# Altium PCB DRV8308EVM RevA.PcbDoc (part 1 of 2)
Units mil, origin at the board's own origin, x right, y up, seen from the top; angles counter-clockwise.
Board outline 4724.41 x 2952.76 mil, 2 copper layers (Top Layer, Bottom Layer), stack 62 mil thick; 110 components, 81 nets, 346 pads, 592 vias.
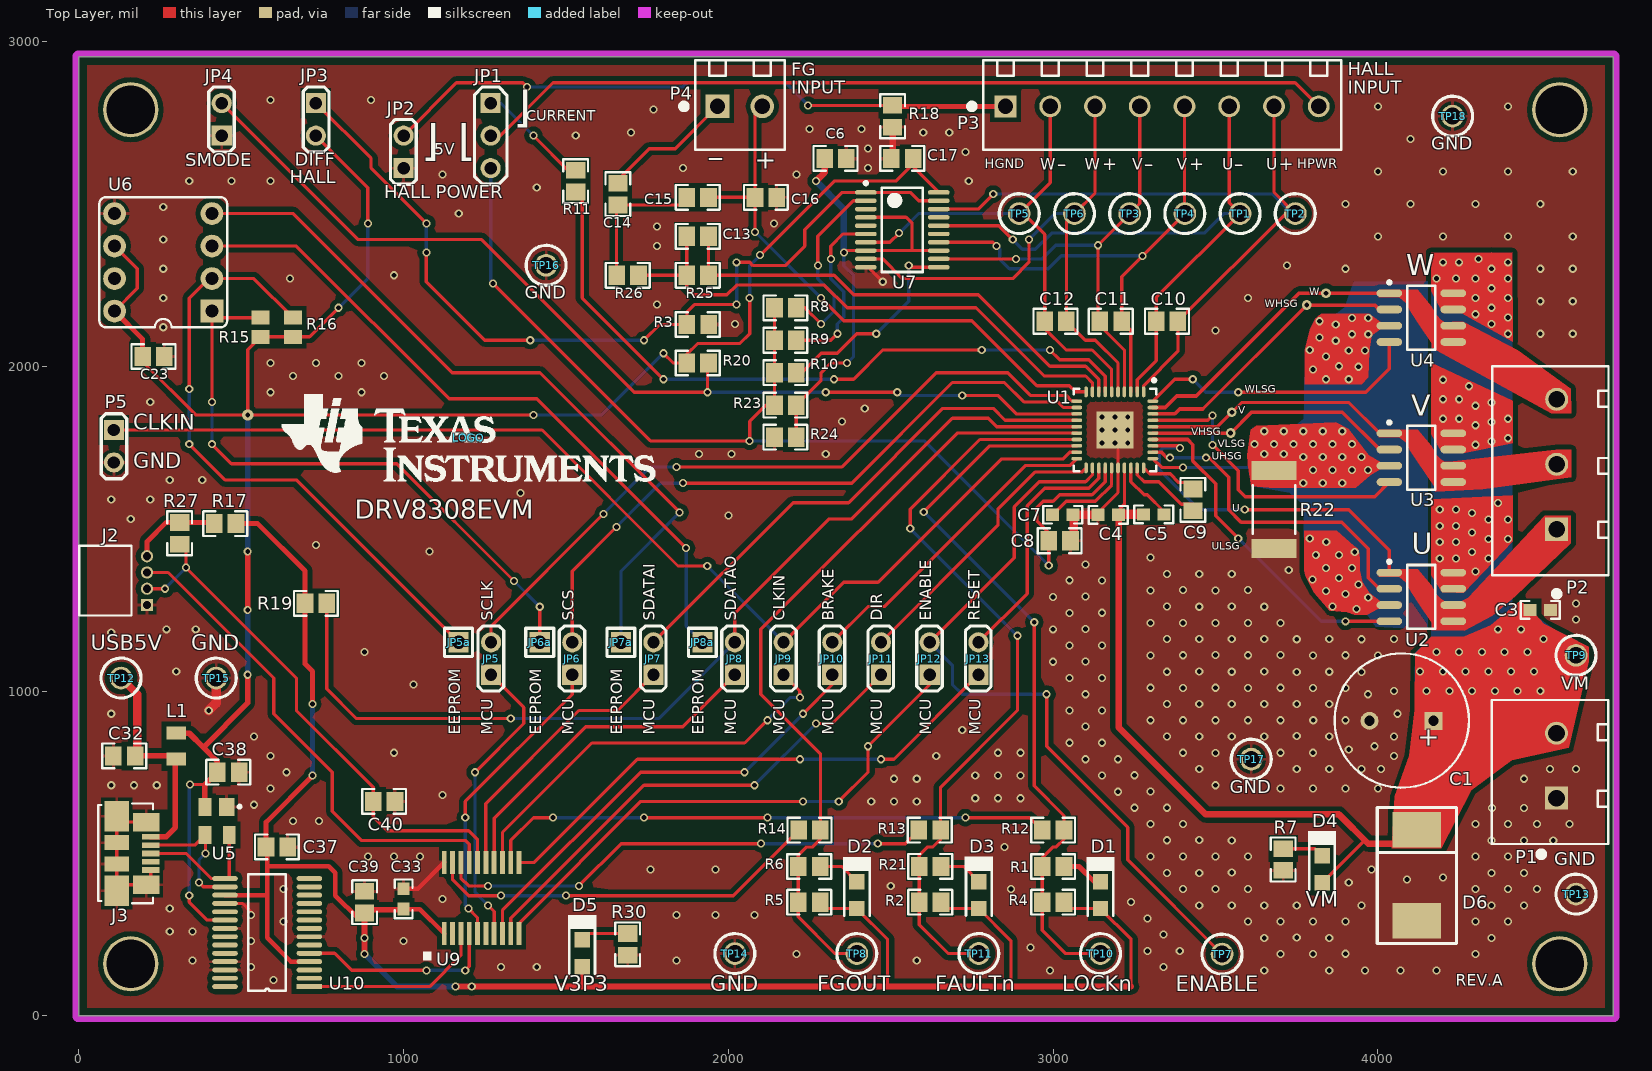
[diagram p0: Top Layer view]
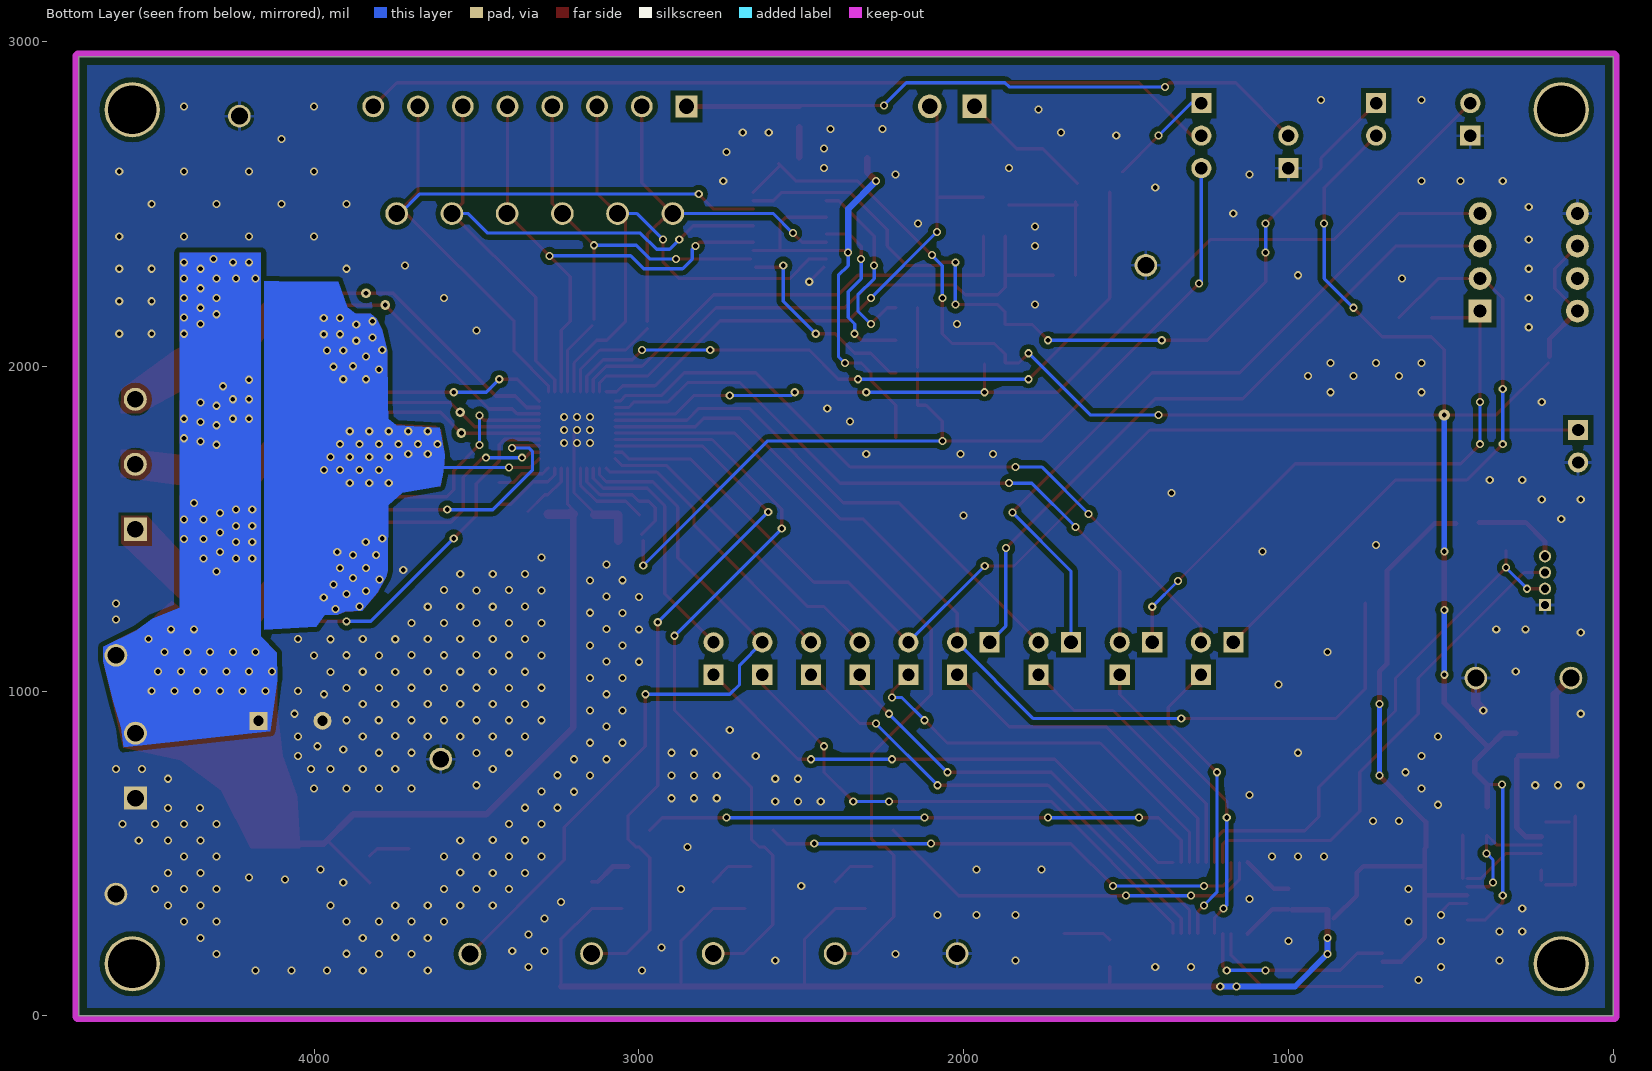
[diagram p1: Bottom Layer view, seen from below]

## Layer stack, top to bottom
Top Layer: signal copper 1.4
Dielectric: core 59.2, FR-4, Dk 4.8
Bottom Layer: signal copper 1.4

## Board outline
0,0 4724.41,0 4724.41,2952.76 0,2952.76

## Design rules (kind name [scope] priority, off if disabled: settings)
AcuteAngle [All] p1: minimum=1.50000000000000E+0001 checktracksonly=FALSE
AssemblyTestPointUsage [All] p1: valid=2
Clearance Clearance_BoardEdge_MountingHoles [OnCopper and InComponentClass('Mounting Holes') vs IsKeepOut] p1: gap=40
Clearance Clearance_BoardEdge_Poly [OnCopper and InPoly vs IsKeepOut] p2: gap=25
Clearance Clearance_BoardEdge [OnCopper and Not InComponentClass('Logo') and not InComponentClass('FiducialMark') and not InRegion(1000,500,4000,800) and Not IsKeepout vs IsKeepOut] p3: gap=75
Clearance Clearance_Poly [InPolygon] p4: gap=15
Clearance [All] p5: gap=8
ComponentClearance ComponentClearance_Logo [InComponentClass('Logo')] p1: gap=50 collisioncheckmode=3 verticalgap=10 showdistances=FALSE
ComponentClearance ComponentClearance_ScrewToNut [(HasFootprint('NY PMS 440 0025 PH')) vs (HasFootprint('Keystone_1902C'))] p2: gap=5 collisioncheckmode=3 verticalgap=10 showdistances=FALSE
ComponentClearance ComponentClearance_MountingHoles [InComponentClass('Mounting Holes')] p3: gap=250 collisioncheckmode=3 verticalgap=100000 showdistances=FALSE
ComponentClearance ComponentClearance_SmallPassives [HasFootprint('0201*') or HasFootprint('0402*') or HasFootprint('0508') or HasFootprint('0603*') or HasFootprint('0612') or HasFootprint('0805*') or HasFootprint('0815*') or HasFootprint('0830*') or HasFootprint('1206*') or HasFootprint('1210*') or HasFootprint('1808*') or HasFootprint('1812*') or HasFootprint('1825*') or HasFootprint('2010*') or HasFootprint('2220*') or HasFootprint('2225*') or HasFootprint('2512*') or HasFootprint('2728*') or HasFootprint('3518*') vs HasFootprint('0201*') or HasFootprint('0402*') or HasFootprint('0508') or HasFootprint('0603*') or HasFootprint('0612') or HasFootprint('0805*') or HasFootprint('0815*') or HasFootprint('0830*') or HasFootprint('1206*') or HasFootprint('1210*') or HasFootprint('1808*') or HasFootprint('1812*') or HasFootprint('1825*') or HasFootprint('2010*') or HasFootprint('2220*') or HasFootprint('2225*') or HasFootprint('2512*') or HasFootprint('2728*') or HasFootprint('3518*')] p4: gap=20 collisioncheckmode=3 verticalgap=10 showdistances=FALSE
ComponentClearance ComponentClearance_THtoSMT [IsThruComponent vs IsSMTComponent] p5: gap=54.33 collisioncheckmode=3 verticalgap=30 showdistances=FALSE
ComponentClearance ComponentClearance_THtoTH [IsThruComponent vs IsThruComponent] p6: gap=0 collisioncheckmode=3 verticalgap=30 showdistances=FALSE
ComponentClearance [All] p7: gap=40 collisioncheckmode=3 verticalgap=10 showdistances=FALSE
DiffPairsRouting [All] p1: maxlimit=100 minlimit=10 mostfreqgap=10 maxuncoupledlength=1000
FabricationTestPointUsage TestPointUsage [All] p1: valid=2 allowmultiple=FALSE
FabricationTestpoint Testpoint [All] p1: side=3 testpointundercomponent=TRUE minsize=40 maxsize=100 preferedsize=60 minholesize=0 maxholesize=40 preferedholesize=32 testpointgrid=1 allowsidetop=TRUE allowsidebottom=TRUE usegrid=TRUE gridtolerance=0.01
FanoutControl Fanout_LCC [IsLCC] p1: bgadir=Out bgaviamode=Centered fanoutstyle=Auto fanoutdirection=Alternating viagrid=1 // Fanout_LCC (Default Rule)
FanoutControl Fanout_BGA [IsBGA] p2: bgadir=Out bgaviamode=Centered fanoutstyle=Auto fanoutdirection=Alternating viagrid=1 // Fanout_BGA (Default Rule)
FanoutControl Fanout_Default [All] p4: bgadir=Out bgaviamode=Centered fanoutstyle=Auto fanoutdirection=Alternating viagrid=1 // Fanout_Default (Default Rule)
FanoutControl Fanout_Small [(CompPinCount < 5)] p5: bgadir=Out bgaviamode=Centered fanoutstyle=Auto fanoutdirection=OutThenIn viagrid=1 // Fanout_Small (Default Rule)
HoleSize [All] p1: absolutevalues=TRUE maxlimit=251 minlimit=8 maxpercent=80.000 minpercent=20.000
MinimumAnnularRing [All] p1: minimumring=5
MinimumSolderMaskSliver MinimumSolderMaskSliver_Logo [InComponentClass('Logo') vs InComponentClass('Logo')] p1: minsoldermaskwidth=0.7
MinimumSolderMaskSliver [All] p2: minsoldermaskwidth=3
PlaneConnect [All] p1: planeconnectstyle=Relief reliefexpansion=10 reliefentries=4 reliefconductorwidth=10 reliefairgap=10
PolygonConnect PolygonConnect_1 [IsNamedPolygon('Top GND plane') or IsNamedPolygon('Bottom GND plane') vs not ( InComponent('U1') or InComponent('C1') or       InComponent('C2') or InComponent('P1') or       InComponent('D6') or InComponent('R22') or       InComponent('TP13') or   InComponent('C3') or       InComponent('U11') or       IsStitchingVia or IsVia)] p1: connectstyle=Relief reliefconductorwidth=10 reliefentries=4 polygonreliefangle="90 Angle" airgapwidth=10
PolygonConnect [All] p2: connectstyle=Direct reliefconductorwidth=10 reliefentries=4 polygonreliefangle="90 Angle" airgapwidth=10
RoutingVias [All] p1: holewidth=16 width=34 viastyle="Through Hole" minholewidth=8 minwidth=25 maxholewidth=40 maxwidth=65
SMDToCorner [All] p1: distance=0
SilkToSilkClearance [All] p1: silktosilkclearance=3
SilkscreenOverComponentPads [All] p1: minsilkscreentomaskgap=2
SolderMaskExpansion [All] p1: expansion=3
Width [All] p1: maxlimit=100 minlimit=6 preferedwidth=10 checkconnectedcopper=TRUE
14 further rules are at their usual default settings.

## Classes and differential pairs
component class Logo: LOGO

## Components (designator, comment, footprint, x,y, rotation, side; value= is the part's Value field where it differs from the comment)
C1 "220uF" UVZ1J221MPD_fp 4080,910 r180 top
C3 "06031C272JAT2A" 0603 4500,1250 r0 top
C4 "06031C272JAT2A" 0603 3169.91,1542.7 r180 top
C5 "06031C272JAT2A" 0603 3309.91,1544.02 r180 top
C6 "" 0805#1 2330,2640 r0 top
C7 "06031C272JAT2A" 0603 3029.91,1542.7 r0 top
C8 "" 0805#1 3019.91,1462.7 r180 top
C9 "" 0805#1 3430.22,1588.43 r90 top
C10 "0.1uF" 0805#1 3350.77,2138.54 r0 top
C11 "0.1uF" 0805#1 3177.46,2138.54 r0 top
C12 "0.1uF" 0805#1 3007.46,2138.54 r0 top
C13 "" 0805#1 1905.51,2400 r0 top
C14 "" 0805#1 1659.75,2530 r270 top
C15 "" 0805#1 1905.51,2520 r180 top
C16 "" 0805#1 2115.51,2520 r180 top
C17 "Cap" 0805#1 2535.51,2639.69 r0 top
C23 "" 0805#1 230,2030 r0 top
C32 "Cap" 0805#1 140,800 r0 top
C33 "06031C272JAT2A" 0603 1000,360 r90 top
C37 "Cap" 0805#1 610,520 r180 top
C38 "" 0805#1 460,750 r0 top
C39 "" 0805#1 880,350 r90 top
C40 "" 0805#1 940,660 r180 top
D1 "LTST-C171GKT" LED_LTST-C171 3145.59,371.59 r90 top
D2 "LTST-C171GKT" LED_LTST-C171 2395.59,371.59 r90 top
D3 "LTST-C170KRKT" LED_LTST-C170 2771.11,371.78 r90 top
D4 "LTST-C171GKT" LED_LTST-C171 3828.24,451.13 r90 top
D5 "LTST-C171GKT" LED_LTST-C171 1550,192.46 r90 top
D6 "1.5SMC33" SMC-W 4119.8,292.63 r90 top
J2 "851-43-004-20-001000" CONN_851-43-004-20-001000 210,1340 r270 top
J3 "0473460001" CONN_47346-0001 60,500 r90 top
JP1 "JUMPER_3X100MIL" HDR100_1X3 1268.03,2810 r270 top
JP2 "JUMPER_2X100MIL" "2PIN HEADER" 1048.03,2564.69 r90 top
JP3 "JUMPER_2X100MIL" "2PIN HEADER" 681.97,2855.31 r270 top
JP4 "JUMPER_2X100MIL" "2PIN HEADER" 488.03,2664.69 r90 top
JP5 "JUMPER_2X100MIL" "2PIN HEADER" 1317.38,1004.68 r90 top
JP5a "PartNumber" "1x1 Header" 1216.72,1103.59 r90 top
JP6 "JUMPER_2X100MIL" "2PIN HEADER" 1567.38,1004.68 r90 top
JP6a "PartNumber" "1x1 Header" 1466.72,1103.59 r90 top
JP7 "JUMPER_2X100MIL" "2PIN HEADER" 1817.38,1004.68 r90 top
JP7a "PartNumber" "1x1 Header" 1716.72,1103.59 r90 top
JP8 "JUMPER_2X100MIL" "2PIN HEADER" 2068.03,1004.68 r90 top
JP8a "PartNumber" "1x1 Header" 1967.38,1103.59 r90 top
JP9 "JUMPER_2X100MIL" "2PIN HEADER" 2218.03,1004.68 r90 top
JP10 "JUMPER_2X100MIL" "2PIN HEADER" 2368.03,1004.68 r90 top
JP11 "JUMPER_2X100MIL" "2PIN HEADER" 2518.03,1004.68 r90 top
JP12 "JUMPER_2X100MIL" "2PIN HEADER" 2668.03,1004.68 r90 top
JP13 "JUMPER_2X100MIL" "2PIN HEADER" 2818.03,1004.68 r90 top
L1 "40Z@100MHz" 0805#2 300,830 r90 top
LOGO "Texas Instruments" TI_Stacked_Overlay_Medium 1200,1780 r0 top
P1 "OSTTA024163" On-Shore_OSTTA024163 4530,750.54 r90 top
P2 "OSTTA034163" On-Shore_OSTTA034163 4530.77,1678.43 r90 top
P3 "OSTTE080161" On-Shore_OSTTE080161 3335.51,2800 r0 top
P4 "OSTTE020161" On-Shore_OSTTE020161 2035.51,2800 r0 top
P5 "JUMPER_2X100MIL" "2PIN HEADER" 59.97,1848.96 r270 top
R1 "390" 0805#1 3000,459.68 r0 top
R2 "10K" 0805#1 2621.43,349.88 r0 top
R3 "10K" 0805#1 1905.83,2128.54 r0 top
R4 "10K" 0805#1 3000,349.68 r0 top
R5 "390" 0805#1 2248.9,349.68 r0 top
R6 "390" 0805#1 2248.9,459.68 r0 top
R7 "Res1" 0805#1 3708.24,481.13 r90 top
R8 "" 0805#1 2175.51,2180 r0 top
R9 "" 0805#1 2175.51,2080 r0 top
R10 "" 0805#1 2175.51,1980 r0 top
R11 "2K" 0805#1 1530,2570 r270 top
R12 "0" 0805#1 3000,571.58 r180 top
R13 "0" 0805#1 2620,571.58 r180 top
R14 "0" 0805#1 2250,571.58 r180 top
R15 "1-1614959-1" 0805L 559.68,2120 r270 top
R16 "1-1614959-1" 0805L 659.68,2120 r270 top
R17 "0" 0805#1 450.63,1515.59 r0 top
R18 "180" 0805#1 2505.51,2769.69 r270 top
R19 "5.1K" 0805#1 730,1270 r180 top
R20 "10K" 0805#1 1905.51,2010 r0 top
R21 "390" 0805#1 2621.43,459.88 r0 top
R22 "PartNumber" 2512M 3680,1558.43 r90 top
R23 "" 0805#1 2175.51,1880 r180 top
R24 "" 0805#1 2175.51,1781.48 r0 top
R25 "820K" 0805#1 1905.51,2280 r180 top
R26 "2K" 0805#1 1690,2280 r180 top
R27 "47K" 0805#1 310.63,1485.59 r270 top
R30 "Res1" 0805#1 1690,220 r90 top
TP1 "TP-LOOP-ORANGE" "TEST POINT 0.052" 3575.51,2470 r0 top
TP2 "TP-LOOP-ORANGE" "TEST POINT 0.052" 3745.51,2470 r0 top
TP3 "TP-LOOP-ORANGE" "TEST POINT 0.052" 3235.51,2470 r0 top
TP4 "TP-LOOP-ORANGE" "TEST POINT 0.052" 3405.51,2470 r0 top
TP5 "TP-LOOP-ORANGE" "TEST POINT 0.052" 2895.51,2470 r0 top
TP6 "TP-LOOP-ORANGE" "TEST POINT 0.052" 3065.51,2470 r0 top
TP7 "TP-LOOP-ORANGE" "TEST POINT 0.052" 3520,190 r0 top
TP8 "TP-LOOP-ORANGE" "TEST POINT 0.052" 2395.59,191.59 r0 top
TP9 "TP-LOOP-ORANGE" "TEST POINT 0.052" 4610,1110 r0 top
TP10 "TP-LOOP-BLACK" "TEST POINT 0.052" 3145.59,191.59 r0 top
TP11 "TP-LOOP-ORANGE" "TEST POINT 0.052" 2771.11,191.78 r0 top
TP12 "TP-LOOP-ORANGE" "TEST POINT 0.052" 130,1040 r0 top
TP13 "TP-LOOP-BLACK" "TEST POINT 0.052" 4610,374.68 r0 top
TP14 "TP-LOOP-BLACK" "TEST POINT 0.052" 2020,191.59 r0 top
TP15 "TP-LOOP-ORANGE" "TEST POINT 0.052" 422.99,1039.9 r0 top
TP16 "TP-LOOP-BLACK" "TEST POINT 0.052" 1438.94,2310.81 r0 top
TP17 "TP-LOOP-BLACK" "TEST POINT 0.052" 3610,790 r0 top
TP18 "TP-LOOP-BLACK" "TEST POINT 0.052" 4230,2770 r0 top
U1 "DRV8308" RHA0040A 3189.91,1804.02 r270 top
U2 "SI4946BEY" SO-8_N 4133.53,1289.63 r0 top
U3 "SI4946BEY" SO-8_N 4133.53,1718.43 r0 top
U4 "SI4946BEY" SO-8_N 4133.53,2149.63 r0 top
U5 "SP0503BAHTG" SOT-143-4 420,600 r270 top
U6 "1-390261-2" TE_1-390261-2 260,2320 r180 top
U7 "SN74CBT3244CPW" PW0020A_N 2535.51,2420 r0 top
U9 "MSP430G2553IPW20" PW20 1240,360 r90 top
U10 "FT232R" FT232RL 710,90 r180 top

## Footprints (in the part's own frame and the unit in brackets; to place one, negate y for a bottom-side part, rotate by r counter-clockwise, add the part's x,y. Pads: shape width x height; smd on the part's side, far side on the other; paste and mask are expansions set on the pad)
"1x1 Header" [mil]
  rect 62x62 hole 42: 1(46.41,47.38)
  silkscreen extent 3,5 90,90
"2PIN HEADER" [mil]
  rect 62x62 hole 38: 1(45.31,48.03)
  round 62 hole 38: 2(145.31,48.03)
  silkscreen extent -5,9 195,88
0603 [mm] "0603 from SM-752 data"
  rect 1x0.95 smd: 1(-0.8,0) 2(0.8,0)
  silkscreen extent -1.52,-0.69 1.52,0.69, body extent -0.87,-0.47 0.87,0.47, height 0.85
0805#1 [mm] "0805 from SM-752 data"
  rect 1.3x1.5 smd: 1(-0.85,0) 2(0.85,0)
  silkscreen extent -1.72,-0.97 1.72,0.97, body extent -1.1,-0.72 1.1,0.72, height 1.1
0805#2 [mm]
  rect 1.016x1.524 smd: 1(-1.016,0) 2(1.016,0)
0805L [mm] "0805 from SM-752 data"
  rect 1.1x1.4 smd: 1(-0.75,0) 2(0.75,0)
  body extent -1.1,-0.72 1.1,0.72, height 1.1
2512M [mm] "Chip Resistor, Body 6.3x3.2mm, IPC Low Density"
  rect 1.5x3.5 smd: 1(-3.05,0) 2(3.05,0)
  silkscreen extent -1.9,-1.65 1.9,1.65, body extent -3.22,-1.67 3.22,1.67, height 0.71
CONN_851-43-004-20-001000 [mm] "MILL-MAX"
  rect 0.95x0.95 hole 0.65: 1(1.905,0)
  round 0.95 hole 0.65: 2(0.635,0) 3(-0.635,0) 4(-1.905,0)
  silkscreen extent -2.73,-5.31 2.73,-1.22, body extent -2.73,-5.31 2.73,0.23, height 2.23
CONN_47346-0001 [mm] "MOLEX"
  rect 0.445x1.38 smd mask+0.043: 1(1.3,-4.105) 2(0.65,-4.105) 3(0,-4.105) 4(-0.65,-4.105) 5(-1.3,-4.105)
  rect 1.448x2.1 smd mask+0.043: 6(-2.45,-3.755) 7(2.45,-3.75)
  rect 2.375x1.9 smd mask+0.043: 8(-2.912,-1.45) 11(2.912,-1.45)
  rect 1.175x1.9 smd mask+0.043: 9(-0.837,-1.45) 10(0.837,-1.45)
  silkscreen extent -3.9,-4.28 3.9,0, body extent -3.99,-4.43 3.99,1, height 2.72
FT232RL [mm]
  rect 2x0.381 smd: 1(0,0)
  oval 2x0.381 smd: 2(0,-0.65) 3(0,-1.3) 4(0,-1.95) 5(0,-2.6) 6(0,-3.25) 7(0,-3.9) 8(0,-4.55) 9(0,-5.2) 10(0,-5.85) 11(0,-6.5) 12(0,-7.15) 13(0,-7.8) 14(0,-8.45) 15(6.6,-8.45) 16(6.6,-7.8) 17(6.6,-7.15) 18(6.6,-6.5) 19(6.6,-5.85) 20(6.6,-5.2) 21(6.6,-4.55) 22(6.6,-3.9) 23(6.6,-3.25) 24(6.6,-2.6) 25(6.6,-1.95) 26(6.6,-1.3) 27(6.6,-0.65) 28(6.6,0)
  silkscreen extent 1.84,-8.78 4.76,0.33
HDR100_1X3 [mil]
  rect 62x62 hole 38: 1(0,0)
  round 62 hole 38: 2(100,0) 3(200,0)
  silkscreen extent -50,-50 250,50
LED_LTST-C170 [mm] "LITE-ON"
  rect 1.2x1.2 smd: 1(-1.05,0) 2(1.05,0)
  silkscreen extent -1.6,-1.1 3,1.1, body extent -1.05,-0.67 1.05,0.67, height 1.1
LED_LTST-C171 [mm] "LITE-ON"
  rect 1.2x1.2 smd: 1(-1.05,0) 2(1.05,0)
  silkscreen extent -1.6,-1.1 3,1.1, body extent -1.05,-0.67 1.05,0.67, height 0.8
On-Shore_OSTTA024163 [mm] "TERM BLOCK 2x1, 5.08mm, TH"
  rect 1.8x1.8 hole 1.3: 1(-2.04,-0.5)
  round 1.8 hole 1.3 paste+0: 2(3.04,-0.5)
  silkscreen extent -6.53,-4.55 5.63,4.55, body extent -5.68,-4.6 5.68,4.6, height 13
On-Shore_OSTTA034163 [mm] "TERM BLOCK 3x1, 5.08mm, TH"
  rect 1.8x1.8 hole 1.3: 1(-4.58,-0.5)
  round 1.8 hole 1.3 paste+0: 2(0.5,-0.5) 3(5.58,-0.5)
  silkscreen extent -9.73,-4.55 8.17,4.55, body extent -8.22,-4.6 8.22,4.6, height 13
On-Shore_OSTTE020161 [mm] "Term Blk 2x1"
  rect 1.85x1.85 hole 1.2: 1(-1.75,0)
  round 1.85 hole 1.2: 2(1.75,0)
  silkscreen extent -4.47,-3.4 3.5,3.6, body extent -3.5,-3.4 3.5,3.6, height 8.4
On-Shore_OSTTE080161 [mm] "Term Blk 8x1"
  rect 1.7x1.7 hole 1.2: 1(-12.25,0)
  round 1.7 hole 1.2: 2(-8.75,0) 3(-5.25,0) 4(-1.75,0) 5(1.75,0) 6(5.25,0) 7(8.75,0) 8(12.25,0)
  silkscreen extent -14.97,-3.4 14,3.6, body extent -14,-3.4 14,3.6, height 8.4
PW20 [mil]
  rect 70x15 smd: 1(-106.7,114.8) 2(-106.7,89.2) 3(-106.7,63.6) 4(-106.7,38) 5(-106.7,12.4) 6(-106.7,-13.2) 7(-106.7,-38.8) 8(-106.7,-64.4) 9(-106.7,-90) 10(-106.7,-115.6) 11(112.3,-115.7) 12(112.3,-90.1) 13(112.3,-64.5) 14(112.3,-38.9) 15(112.3,-13.3) 16(112.3,12.3) 17(112.3,37.9) 18(112.3,63.5) 19(112.3,89.1) 20(112.3,114.8)
  silkscreen extent -188,155 -163,180
PW0020A_N [mm] "TSOP, 20-Leads, Body 6.5x4.4mm, Pitch 0.65mm, IPC Medium Density"
  oval 1.7x0.35 smd: 1(-2.85,2.925) 2(-2.85,2.275) 3(-2.85,1.625) 4(-2.85,0.975) 5(-2.85,0.325) 6(-2.85,-0.325) 7(-2.85,-0.975) 8(-2.85,-1.625) 9(-2.85,-2.275) 10(-2.85,-2.925) 11(2.85,-2.925) 12(2.85,-2.275) 13(2.85,-1.625) 14(2.85,-0.975) 15(2.85,-0.325) 16(2.85,0.325) 17(2.85,0.975) 18(2.85,1.625) 19(2.85,2.275) 20(2.85,2.925)
  silkscreen extent -2.97,-3.3 1.6,3.77, body extent -2.25,-3.3 2.25,3.3, height 1.2
RHA0040A [mm] "QFN, 40-Leads, Body 6x6mm, Pitch 0.5mm, Thermal Pad 2.9x2.9mm, TI Recommended"
  oval 0.85x0.28 smd paste-0.025 mask+0.07: 1(-2.975,2.25) 2(-2.975,1.75) 3(-2.975,1.25) 4(-2.975,0.75) 5(-2.975,0.25) 6(-2.975,-0.25) 7(-2.975,-0.75) 8(-2.975,-1.25) 9(-2.975,-1.75) 10(-2.975,-2.25) 21(2.975,-2.25) 22(2.975,-1.75) 23(2.975,-1.25) 24(2.975,-0.75) 25(2.975,-0.25) 26(2.975,0.25) 27(2.975,0.75) 28(2.975,1.25) 29(2.975,1.75) 30(2.975,2.25)
  oval 0.28x0.85 smd paste-0.025 mask+0.07: 11(-2.25,-2.975) 12(-1.75,-2.975) 13(-1.25,-2.975) 14(-0.75,-2.975) 15(-0.25,-2.975) 16(0.25,-2.975) 17(0.75,-2.975) 18(1.25,-2.975) 19(1.75,-2.975) 20(2.25,-2.975) 31(2.25,2.975) 32(1.75,2.975) 33(1.25,2.975) 34(0.75,2.975) 35(0.25,2.975) 36(-0.25,2.975) 37(-0.75,2.975) 38(-1.25,2.975) 39(-1.75,2.975) 40(-2.25,2.975)
  rect 2.9x2.9 smd paste-2.45 mask+0.07: 41(0,0)
  silkscreen extent -4,-3.22 3.22,3.22, body extent -3.08,-3.08 3.08,3.08, height 1
SMC-W [mil]
  rect 110x150 smd: 1(0,0) 2(280,0)
  silkscreen extent -70,-122 349,122
SO-8_N [mm] "SOIC, 8-Leads, Body 4.9x3.9mm, Pitch 1.27mm, IPC Medium Density"
  oval 2x0.6 smd: 1(-2.5,1.905) 2(-2.5,0.635) 3(-2.5,-0.635) 4(-2.5,-1.905) 5(2.5,-1.905) 6(2.5,-0.635) 7(2.5,0.635) 8(2.5,1.905)
  silkscreen extent -2.62,-2.5 1.1,2.88, body extent -2,-2.5 2,2.5, height 1.75
SOT-143-4 [mm] "Littelfuse"
  rect 1.4x1.2 smd: 1(-1.1,0.9)
  rect 1.4x1 smd: 2(-1.1,-0.8) 3(1.1,-0.8) 4(1.1,1.1)
  silkscreen extent -1.22,1.8 -1.02,2.01, body extent -0.7,-1.52 0.7,1.52, height 1.23
TE_1-390261-2 [mil] "TE Socket, DIP 8 Pos."
  rect 70x70 hole 40 mask+2.56: 1(-150,150)
  round 70 hole 40 mask+2.56: 2(-150,50) 3(-150,-50) 4(-150,-150) 5(150,-150) 6(150,-50) 7(150,50) 8(150,150)
  silkscreen extent -197,-200 197,200, body extent -197,-200 197,200, height 201
"TEST POINT 0.052" [mil] "Glass Beaded Test Point"
  round 70 hole 52: 1(0,0)
  silkscreen extent -61,-61 62,61
TI_Stacked_Overlay_Medium [mil]
  silkscreen extent -576,-136 576,134
UVZ1J221MPD_fp [mm] "220uF footprint"
  rect 1.4x1.4 hole 0.8: 1(-2.31,0.045)
  round 1.4 hole 0.8: 2(2.69,0.045)
  silkscreen extent -5.09,-5.23 5.41,5.27, body extent -5.02,-5.2 5.43,5.29, height 27.01

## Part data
C1: library part UVZ1J221MPD
C3 C4 C5 C7 C33: "CAP, CERM, 2700pF, 100V, +/-5%, X7R, 0603"
C6 C8 C9 C10 C11 C12 C13 C14 C15 C16 C23 C38 C39 C40: library part Cap, "Capacitor"
C17 C32 C37: "Capacitor"
D1 D2 D4 D5: "LED, Green, SMD"
D3: "LED, Red, SMD"
D6: library part "D Schottky", "Schottky Diode"
J2: library part 851-43-004-20-001000_nosilk, "MSP430 programming connector"
J3: library part "USB Micro B"
JP1: "Header, Male 3-pin, 100mil spacing,"
JP2 JP3 JP4 JP5 JP6 JP7 JP8 JP9 JP10 JP11 JP12 JP13 P5: "Header, Male 2-pin, 100mil spacing,"
JP5a JP6a JP7a JP8a: library part "1x1 Header", "1x1 Header"
L1: library part BEAD_FERRITE_MPZ2012_SERIES, "Bead, Ferrite, yymA, yyOhm @100KHz"
LOGO: library part TI_Logo, "Texas Instrument Corporate Signature"
P1: "Terminal Block, 2x1, 5.08mm, TH"
P2: "Terminal Block, 3x1, 5.08 mm, TH"
P3: "Terminal Block, 8x1, 3.5mm, TH"
P4: "Terminal Block, 2x1, 3.5mm, TH"
R1 R2 R3 R4 R5 R6 R8 R9 R10 R11 R12 R13 R14 R17 R18 R19 R20 R21 R23 R24 R25 R26 R27: library part Res1, "Resistor"
R7 R30: "Resistor"
R15 R16: "RES, 1.50Meg ohm, 0.1%, 0.1W, 0805"
R22: library part CSRN2512FK30L0, "RES, 0.03 ohm, 1%, 2W, 2512"
TP1 TP2 TP3 TP4 TP5 TP6 TP7 TP8 TP9 TP10 TP11 TP12 TP13 TP14 TP15 TP16 TP17 TP18: library part "TEST POINT", "Glass Beaded Test Point"
U2 U3 U4: library part FDS8949, "MOSFET N-CH DUAL 30V 3.5A SOP8"
U5: "Diode, TVS, Uni, 5.5V, W, 3.04X1.22X1.4"
U6: "Socket, DIP-8 TIN, TH"
U9: library part MSP430G2553IPW20_sm
U10: "USB Chip"

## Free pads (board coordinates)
  round 170 hole 150: 0(160,160) 0(160,2790) 0(4560,160) 0(4560,2790)

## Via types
v1: diameter 25, hole 15, Top Layer to Bottom Layer, tented both sides, 582 vias
v2: diameter 25, hole 15, Top Layer to Bottom Layer, tented bottom, 5 vias
v3: diameter 30, hole 15, Top Layer to Bottom Layer, tented bottom, 4 vias
v4: diameter 35, hole 15, Top Layer to Bottom Layer, tented both sides, 1 vias

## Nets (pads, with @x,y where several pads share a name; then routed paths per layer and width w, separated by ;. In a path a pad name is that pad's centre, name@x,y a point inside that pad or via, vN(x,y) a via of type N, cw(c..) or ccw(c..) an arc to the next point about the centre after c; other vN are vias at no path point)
2V: C6.1 R23.1 R24.2 U7.4 U7.8 U7.13 | length 1548.3
  Top Layer w10: R24.2@2208.98,1781.48 R23.1@2208.98,1880 2285.51,1956.54 2285.51,1980 2315.51,2010 v1(2365.51,2010) ; v1(2355.51,2350) 2361.54,2356.02 U7.8@2423.31,2356.02 2565.51,2356.02 ; U7.4@2423.31,2458.39 2547.13,2458.39 2565.51,2440 2565.51,2356.02 ; U7.13@2647.72,2356.02 2565.51,2356.02
  Top Layer w20: v1(2270,2570) 2296.54,2596.54 C6.1@2296.54,2640
  Bottom Layer w10: v1(2355.51,2350) 2355.51,2310 2385.51,2280 2385.51,2030 v1(2365.51,2010)
  Bottom Layer w20: v1(2270,2570) 2355.51,2484.49 v1(2355.51,2350)
5VCC: C17.2 C23.1 C38.1 JP3.2 L1.2 R15.2 R16.2 R20.1 U5.2 U6.6 U6.8 U7.20 U10.20 | length 6572.7
  Top Layer w10: U6.8@110,2170 180,2240 180,2300 U6.6@110,2370 ; C23.1@200,2010 360,1850 v4(520,1850) ; v1(340,370) 340,350 395.28,294.72 U10.20@450.16,294.72 ; v1(341.97,711.97) 388.5,711.97 ; JP3.2@730,2710 890,2550 v1(890,2440) ; v1(800,2180) 710.47,2090.47 R16.2@659.68,2090.47 R15.2@559.68,2090.47 520,2050.79 v4(520,1850) ; v1(1400,1850) v4(520,1850) ; v1(1800,2040) 1830,2010 R20.1@1872.05,2010 1872.05,2036.54 1905.51,2070 2035.51,2070 2065.51,2100 v1(2065.51,2210) ; v1(2097.76,2342.24) 2325.51,2570 2515.51,2570 C17.2@2568.98,2623.46 ; C17.2@2568.98,2613.9 U7.20@2647.72,2535.16
  Top Layer w15: U6.8@110,2170 196.54,2083.46 C23.1@196.54,2030
  Top Layer w17: L1.2@300,870 340,870 383.27,826.73 ; U5.2@388.5,643.31 388.5,711.97 C38.1@426.54,750 426.54,783.46 383.27,826.73 ; v1(520,1050) 520,963.46 383.27,826.73 ; v1(520,1250) v1(520,1430)
  Bottom Layer w10: v1(340,370) 340,710 v1(341.97,711.97) ; v1(800,2180) 890,2270 v1(890,2440) ; v1(1400,1850) 1610,1850 v1(1800,2040) ; v1(2065.51,2210) 2065.51,2310 v1(2097.76,2342.24)
  Bottom Layer w17: v1(520,1050) v1(520,1250) ; v1(520,1430) v4(520,1850)
BRAKE: JP10.2 U1.20 | length 987
  Top Layer w10: JP10.2@2320,1150 2430,1260 2480,1260 2914.02,1694.02 3051.36,1694.02 U1.20@3072.78,1715.43
BRAKE_MSP430: JP10.1 U9.8 | length 1404.8
  Top Layer w10: U9.8@1304.4,253.3 1304.4,324.4 1730,750 v1(2050,750) ; v1(2230,930) 2320,1020 JP10.1@2320,1050
  Bottom Layer w10: v1(2050,750) v1(2230,930)
CLKIN: JP9.2 P5.1 U1.19 | length 3477.9
  Top Layer w10: P5.1@108,1803.65 1426.35,1803.65 1845,1385 v1(1935,1385) ; JP9.2@2170,1150 2355,1335 2460.98,1335 2840,1714.02 3029.91,1714.02 3051.01,1735.12 U1.19@3072.78,1735.12
  Bottom Layer w10: v1(1935,1385) JP9.2@2170,1150
CLKIN_MSP430: JP9.1 U9.13 | length 1270.5
  Top Layer w10: U9.13@1304.5,472.3 1304.5,564.5 1580,840 2050,840 v1(2120,910) ; JP9.1@2170,1050 2220,1000 v1(2220,980)
  Bottom Layer w10: v1(2120,910) 2190,980 v1(2220,980)
CP1: C9.2 U1.30 | length 170.4
  Top Layer w10: U1.30@3278.49,1686.89 3296.65,1668.73 3360.22,1668.73 3387.06,1641.89 C9.2@3430.22,1641.89
CP2: C9.1 U1.29 | length 230.5
  Top Layer w10: U1.29@3258.8,1686.89 3258.8,1665.12 3279.91,1644.02 3325.81,1644.02 3394.87,1574.96 C9.1@3430.22,1574.96
DIR: JP11.2 U1.21 | length 883
  Top Layer w10: JP11.2@2470,1150 2830,1510 2830,1560 2944.02,1674.02 3088.45,1674.02 U1.21@3101.32,1686.89
DIR_MSP430: JP11.1 U9.9 | length 1497.4
  Top Layer w10: U9.9@1330,253.3 1330,300 1740,710 v1(2080,710) ; v1(2270,900) 2320,900 JP11.1@2470,1050
  Bottom Layer w10: v1(2080,710) v1(2270,900)
ENABLE: JP12.2 TP7.1 U1.22 | length 2313.1
  Top Layer w10: JP12.2@2620,1150 2880,1410 2880,1566.78 2957.24,1644.02 3099.91,1644.02 3121.01,1665.12 U1.22@3121.01,1686.89 ; v1(2980,990) 2980,830 3230,580 3230,480 TP7.1@3520,190
  Bottom Layer w10: JP12.2@2620,1150 2690,1080 2690,1020 2720,990 v1(2980,990)
ENABLE_MSP430: JP12.1 U9.10 | length 1677.8
  Top Layer w10: U9.10@1355.6,253.3 1355.6,285.6 1730,660 v1(2230,660) ; v1(2340,660) 2430,750 v1(2430,830) 2620,1020 JP12.1@2620,1050
  Bottom Layer w10: v1(2230,660) v1(2340,660)
FAULTN: R2.1 R13.1 R21.1 TP11.1 U1.17 | length 2372.5
  Top Layer w10: v1(2560,1500) 2560,1560 2774.49,1774.49 U1.17@3072.78,1774.49 ; TP11.1@2771.11,191.78 2676.8,191.78 2587.96,280.61 R2.1@2587.96,349.88 R21.1@2587.96,459.88 2587.96,494.51 2613.45,520 2630,520 2653.46,543.46 R13.1@2653.46,571.58 2653.46,703.46 2890,940 v1(2890,1170)
  Bottom Layer w10: v1(2560,1500) v1(2890,1170)
FAULTN_MSP430: R13.2 U9.18 | length 1539.6
  Top Layer w10: U9.18@1176.5,472.3 1176.5,423.5 1200,400 v1(1260,400) ; v1(1540,400) 1670,530 v1(2100,530) ; v1(2460,530) 2544.95,530 R13.2@2586.54,571.58
  Bottom Layer w10: v1(1260,400) v1(1540,400) ; v1(2100,530) v1(2460,530)
FGFB: C13.2 R25.1 U1.8 | length 1492.7
  Top Layer w10: C13.2@1938.98,2400 R25.1@1938.98,2280 2325.51,2280 2385.51,2220 2770,2220 2990,2000 3100,2000 3140.69,1959.31 U1.8@3140.69,1921.14
FGIN+: C15.1 C16.2 P4.2 U1.10 | length 1762.1
  Top Layer w10: C15.1@1938.98,2520 C16.2@2082.05,2520 ; v1(2082.05,2413.46) C16.2@2082.05,2520 ; P4.2@2104.41,2800 2082.05,2777.64 C16.2@2082.05,2520 ; v1(2285.51,2210) 2355.51,2140 2750,2140 2950.15,1939.85 3050.15,1939.85 3068.86,1921.14 U1.10@3101.32,1921.14
  Bottom Layer w10: v1(2082.05,2413.46) v1(2285.51,2210)
FGIN-: C13.1 R25.2 R26.1 U1.9 | length 1728.8
  Top Layer w10: R26.1@1723.46,2280 R25.2@1872.05,2280 ; C13.1@1872.05,2400 R25.2@1872.05,2280 ; U1.9@3121.01,1921.14 3121.01,1948.99 3100,1970 2972.52,1970 2762.52,2180 2365.51,2180 2295.51,2250 2025.51,2250 1995.51,2220 1895.51,2220 1872.05,2243.46 R25.2@1872.05,2280
FGOUT: R5.1 R6.1 R14.1 TP8.1 U1.16 | length 2442.5
  Top Layer w10: R14.1@2283.46,563.46 2283.46,543.46 2260,520 2241.11,520 2215.43,494.32 R6.1@2215.43,459.68 R5.1@2215.43,349.68 2215.43,304.57 2328.41,191.59 TP8.1@2395.59,191.59 ; R14.1@2283.46,571.58 2283.46,806.54 2100,990 2100,1190 2704.17,1794.17 U1.16@3072.78,1794.17
FGOUT_MSP430: R14.2 U9.19 | length 1222.7
  Top Layer w10: U9.19@1150.9,472.3 1150.9,419.1 1200,370 v1(1300,370) ; v1(1500,370) 2014.95,370 R14.2@2216.54,571.58
  Bottom Layer w10: v1(1300,370) v1(1500,370)
GND: C1.2 C3.2 C4.2 C6.2 C7.2 C8.1 C16.1 C17.1 C23.2 C32.1 C33.2 C37.1 C38.2 C39.2 C40.1 D6.1 J2.1 J3.5 J3.6 J3.7 J3.8 J3.9 J3.10 J3.11 JP2.1 JP4.1 P1.1 P5.2 R3.2 R7.1 R18.2 R22.1 R24.1 R30.1 TP13.1 TP14.1 TP15.1 TP16.1 TP17.1 TP18.1 U1.26 U1.41 U5.1 U6.5 U7.10 U9.20 U10.7 U10.18 U10.21 U10.25 U10.26 | length 1347.3
  Top Layer w10: J3.8@117.09,403.54 J3.9@117.09,467.05 J3.10@117.09,532.95 J3.11@117.09,614.65 ; J3.8@123.54,403.54 J3.6@207.83,403.54 ; J3.11@135.28,596.46 J3.7@207.64,596.46 ; J3.6@221.61,417.32 J3.5@221.61,448.82 ; U10.18@450.16,345.91 504.09,345.91 530,320 v1(530,310) ; U7.10@2430.67,2304.84 v1(2475.51,2260) ; C4.2@3138.41,1549.74 3199.75,1611.08 U1.26@3199.75,1686.89 U1.41@3199.75,1794.17
  Top Layer w14: C33.2@1000,391.5 1044.4,391.5 U9.20@1125.2,472.3
  Top Layer w20: C17.1@2505.51,2643.15 R18.2@2505.51,2736.22
  Top Layer w25: C8.1@3063.37,1462.7 C7.2@3063.37,1540.73 ; C7.2@3063.37,1542.7 C4.2@3138.41,1542.7
  Top Layer w30: v1(400,940) 422.99,962.99 TP15.1@422.99,1039.9
  other v1: 600,110 2990,140 3650,140 3850,140 3960,140 4070,140 4180,140 530,150 1300,150 1410,150 3340,150 350,170 1840,170 2580,170 2210,190 3700,190 3800,190 4300,190 3900,191.09 3290,200 3390,200 2930,210 530,230 1000,230 3650,240 3850,240 4350,240 3750,240.54 3340,250 280,260 350,260 630,290 3600,290 3700,290 3800,290 3900,290 4300,290 4400,290 3290,299.46 1840,310 1960,310 2080,310 280,330 3450,340 3550,340 3650,340 3750,340 3950,340 4350,340 4450,340 3240,350 1120,360 630,390 2870,390 3400,390 4300,390 4400,390 4490,390 3500,390.54 3600,390.54 2500,400 3910,410 4090,420 4200,425.48 3350,440 3450,440 4350,440 4450,440 3550,441.09 1760,450 1960,450 3980,450 890,490 970,490 1050,490 3300,490 3600,490 4300,490 4400,490 3400,490.54 3500,490.54 2850,520 3550,540 4350,540 4450,540 4540,540 3350,540.54 3450,541.09 3300,590 4300,590 4400,590 4490,590 4590,590 3400,591.09 660,600 740,600 4350.87,640 4450,640 3250,640.54 3350,640.54 540,650 2440,660 2510,660 2580,660 2760,670 2830,670 2900,670 1120,680 3200,690 3300,691.09 590,700 3700,700 3800,700 3900,700 4000,700 100,710 170,710 240,710 3500,710 2510,730 2580,730 4450,730 3150,739.46 2760,740 2830,740 2900,740 3250,740.54 640,750 3450,760 3750,760 3850,760 3950,760 4010,760 4530,760 4610,760 3100,790 3200,790 590,800 2640,800 4050,800 3500,809.46 970,810 2830,810 2900,810 3400,810 3700,810 3800,810 3910,820 3990,830 3050,840.54 3150,840.54 3450,859.46 540,860 3350,860 3550,860 3650,860 3850,860 4050,860 3750,861.63 2720,880 3100,890.54 3300,910 3400,910 3500,910 3600,910 3700,910 3800.87,910 3900,910 100,930 4060,930 3150,940 3050,940.54 3350,960 3450,960 3650,960 3750,960 3850,960 3550,960.54 3100,990 3970,990 4050,1000 3400,1009.46 3600,1009.46 3800,1008.91 3900,1009.46 3300,1010 3500,1010 3700,1010 1030,1020 3050,1040 3150,1040.54 3350,1059.46 3550,1059.46 3750,1058.91 3850,1059.46 3950,1058.91 300,1060 3450,1060 3650,1060 3000,1090 3100,1090.54 3300,1109.46 3800,1109.46 4000,1109.46 3400,1110 3600,1110 3900,1110 3500,1110.54 3700,1110.54 880,1120 3050,1140.54 3150,1140.54 3750,1159.46 3950,1159.46 3350,1160 3550,1160 3850,1160 4050,1160 3450,1160.54 3650,1160.54 100,1180 270,1190 360,1190 3000,1190 3100,1190.54 3500,1209.46 3300,1210 3400,1210 3600,1210 3700,1210 4610,1220 3050,1240.54 3150,1241.09 3450,1259.46 3650,1259.46 3350,1260 3550,1260 4610,1270 3000,1290 3100,1291.09 3300,1310 3500,1310 3400,1310.54 3600,1310.54 3150,1340 3050,1341.09 3450,1360 3350,1360.54 3550,1360.54 3725.4,1372.66 3100,1390 3300,1410.54 1080,1430 730,1450 160,1530 2000,1540 100,1590 220,1590 1360,1610 280,1650 380,1650 1910,1730 2010,1730 2300,1730 3149.91,1764.02 3189.91,1764.02 3229.91,1764.02 3149.91,1804.02 3189.91,1804.02 3229.91,1804.02 2350,1830 3149.91,1844.02 3189.91,1844.02 3229.91,1844.02 2420,1870 220,1890 590,1920 870,1920 660,1970 800,1970 940,1970 590,2010 730,2010 870,2010 4500,2100 4600,2100 3500,2110 260,2119.99 2020,2130 1780,2190 4500,2200 4600,2200 260,2210 3600,2210 650,2270 970,2280 260,2300 3900,2300 4500,2300 4600,2300 3720,2310 1780,2370 260,2390 4000,2400 4200,2400 4400,2400 4600,2400 1780,2430 2140,2440 1170,2470 260,2490 3900,2500 4100,2500 4300,2500 4500,2500 1410,2550 340,2570 470,2570 590,2570 2740,2570 1120,2590 2210,2590 4000,2600 4200,2600 4400,2600 4600,2600 1860,2610 2430,2610 2730,2660 2430,2670 4100,2700 1530,2710 1700,2720 2600,2720 2680,2720 2250,2730 2410,2730 1770,2790 4000,2800 4400,2800 590,2820 900,2820
HGND: JP2.2 P3.1 R18.1 | length 1960
  Top Layer w10: JP2.2@1000,2710 1162.76,2872.76 1367.24,2872.76 v1(1380,2860) ; v1(2245.76,2803.15) R18.1@2505.51,2803.15
  Top Layer w15: R18.1@2505.51,2800 P3.1@2853.23,2800
  Bottom Layer w10: v1(1380,2860) 1860,2860 1872.76,2872.76 2176.15,2872.76 v1(2245.76,2803.15)
HPWR: JP1.2 P3.8 | length 2647.3
  Top Layer w10: JP1.2@1268.03,2710 1297.24,2710 1460,2872.76 3745.04,2872.76 P3.8@3817.8,2800
ISENSE: R22.2 U1.31 U2.3 U3.3 U4.3 | length 354.9
  Top Layer w10: U1.31@3307.03,1715.43 3334.04,1688.43 v1(3400.22,1688.43)
  Bottom Layer w10: v1(3400.22,1688.43) 3650.77,1688.43
  other v1: 3933.81,1252.86 3860,1260 3970.22,1288.43 3900.22,1298.43 3840.22,1308.43 3940.22,1328.43 3798.77,1343.04 3880.22,1348.43 3840.22,1378.43 3920.22,1378.43 3808.77,1418.43 3880.22,1418.43 3928.58,1428.12 3840.77,1458.43 3790,1470 3770,1640 3830,1640 3890,1640 3800,1680 3860,1680 3920,1680 3970,1680 3770,1720 3830,1720 3890,1720 3950,1720 3650,1730 3710,1730 3620,1760 3680,1760 3740,1760 3800,1760 3860,1760 3920,1760 3650,1800 3710,1800 3770,1800 3830,1800 3890,1800 3840,1960 3910,1960 3800,1990 3940.22,1998.43 3880,2000 3840,2030 3910.22,2048.43 3960.22,2048.43 3790,2050 3870.22,2078.43 3820.22,2088.43 3920.22,2098.43 3970.22,2098.43 3870.22,2128.43 3820.22,2138.43 3920.22,2148.43 3970.22,2148.43
LOCKN: R1.1 R4.1 R12.1 TP10.1 U1.18 | length 2264.7
  Top Layer w10: v1(2601.73,1551.73) 2804.8,1754.8 U1.18@3072.78,1754.8 ; v1(2941.73,1211.73) 2941.73,708.27 3033.46,616.54 R12.1@3033.46,571.58 3033.46,543.46 3010,520 3000,520 2966.54,486.54 R1.1@2966.54,459.68 R4.1@2966.54,349.68 2966.54,263.46 3038.41,191.59 TP10.1@3145.59,191.59
  Bottom Layer w10: v1(2601.73,1551.73) v1(2941.73,1211.73)
LOCKN_MSP430: R12.2 U9.12 | length 1749.1
  Top Layer w10: U9.12@1330.1,472.3 1330.1,540.1 1400,610 v1(1460,610) ; v1(1740,610) v1(2120,610) ; v1(2730,610) 2928.12,610 R12.2@2966.54,571.58
  Bottom Layer w10: v1(1460,610) v1(1740,610) ; v1(2120,610) v1(2730,610)
NetC14_1: C14.1 P4.1 | length 414.6
  Top Layer w10: C14.1@1650,2563.46 1756.54,2670 1836.61,2670 P4.1@1966.61,2800
NetC14_2: C14.2 C15.2 R26.2 | length 438.9
  Top Layer w10: C14.2@1650,2496.54 C14.2@1655.51,2496.54 ; R26.2@1655.51,2280 C14.2@1655.51,2496.54 ; C14.2@1655.51,2506.69 C14.2@1655.51,2496.54 ; C15.2@1862.2,2496.54 C14.2@1655.51,2496.54
NetD1_2: D1.2 R1.2 | length 131.5
  Top Layer w10: D1.2@3126.45,412.92 D1.2@3145.59,412.92
  Top Layer w15: R1.2@3033.46,459.68 3079.68,459.68 D1.2@3126.45,412.92
NetD2_2: D2.2 R6.2 | length 132.6
  Top Layer w10: R6.2@2282.36,459.68 2348.83,459.68 D2.2@2395.59,412.92
NetD3_2: D3.2 R21.2 | length 135.6
  Top Layer w10: R21.2@2654.89,459.88 2724.35,459.88 D3.2@2771.11,413.12
NetD4_2: D4.2 R7.2 | length 129.2
  Top Layer w10: R7.2@3708.24,514.6 3806.12,514.6 D4.2@3828.24,492.47
NetD5_2: D5.2 R30.2 | length 148.1
  Top Layer w10: D5.2@1550,233.8 1569.66,253.46 R30.2@1690,253.46
NetJP1_1: JP1.1 R11.1 | length 332.1
  Top Layer w10: v1(1400,2710) R11.1@1512.2,2597.8
  Bottom Layer w10: JP1.1@1268.03,2810 1300,2810 v1(1400,2710)
OE#: JP3.1 R3.1 U7.1 U7.19 | length 2678.4
  Top Layer w10: JP3.1@730,2810 900,2640 900,2610 v1(1070,2440) ; v1(1070,2350) 1070,2260 1250,2080 v1(1390,2080) ; v1(1740,2080) 1788.54,2128.54 R3.1@1872.36,2128.54 1872.36,2166.85 1895.51,2190 v1(2025.51,2190) ; v1(2025.51,2320) 2065.51,2320 2075.51,2310 2175.51,2310 2235.51,2370 2235.51,2420 2350.67,2535.16 U7.1@2423.31,2535.16 2560.35,2535.16 2585.94,2509.57 U7.19@2647.72,2509.57
  Bottom Layer w10: v1(1070,2350) v1(1070,2440) ; v1(1390,2080) v1(1740,2080) ; v1(2025.51,2190) v1(2025.51,2320)
RESET: JP13.2 U1.23 | length 770
  Top Layer w10: JP13.2@2770,1150 2920,1300 2920,1570 2974.02,1624.02 3109.91,1624.02 3140.69,1654.8 U1.23@3140.69,1686.89
RESET_MSP430: JP13.1 U9.11 | length 1653.6
  Top Layer w10: U9.11@1355.7,472.3 1402.3,472.3 1720,790 v1(2220,790) ; v1(2470,790) 2510,790 JP13.1@2770,1050
  Bottom Layer w10: v1(2220,790) v1(2470,790)
RX: U9.4 U10.5 | length 620
  Top Layer w10: U10.5@710,192.36 787.64,192.36 840,140 v1(1070,140) ; v1(1190,140) 1202,152 U9.4@1202,253.3
  Bottom Layer w10: v1(1070,140) v1(1190,140)
SBWCK: J2.3 U9.17 | length 1529.2
  Top Layer w10: J2.3@210,1365 275,1365 600,1040 600,930 780,750 780,630 870,540 1190,540 1202.1,527.9 U9.17@1202.1,472.3
SBWTDIO: C40.2 J2.2 R27.2 U9.16 | length 1625.7
  Top Layer w10: J2.2@210,1315 v1(265,1315) ; R27.2@330,1432.76 v1(330,1380) 670,1040 670,940 906.54,703.46 C40.2@906.54,660 906.54,613.46 950,570 1200,570 1227.7,542.3 U9.16@1227.7,472.3
  Bottom Layer w10: v1(265,1315) v1(330,1380)
SCLK: JP5.2 U1.11 | length 2212.3
  Top Layer w10: JP5.2@1269.35,1150 1269.35,1199.35 v1(1615,1545) ; v1(1840,1690) 2350,1690 2640,1980 2860,1980 2930,1910 3040,1910 3057.4,1892.6 U1.11@3072.78,1892.6
  Bottom Layer w10: v1(1615,1545) 1760,1690 v1(1840,1690)
SCLK_EEPROM: JP5a.1 R16.1 U6.2 | length 1926.5
  Top Layer w10: v1(340,1760) 450,1650 669.35,1650 JP5a.1@1169.35,1150 ; v1(340,1930) 340,2210 400,2270 U6.2@410,2270 539.21,2270 R16.1@659.68,2149.53
  Bottom Layer w10: v1(340,1760) v1(340,1930)
SCLK_MSP430: JP5.1 U9.7 | length 924.9
  Top Layer w10: v1(1220,750) 1370,900 1370,949.35 JP5.1@1269.35,1050 ; v1(1260,340) 1278.8,321.2 U9.7@1278.8,253.3
  Bottom Layer w10: v1(1220,750) 1220,380 v1(1260,340)
SCS: JP6.2 U1.12 | length 2045.2
  Top Layer w10: JP6.2@1519.35,1150 1519.35,1369.35 v1(1655,1505) ; v1(1860,1640) 2380,1640 2690,1950 2850,1950 2910,1890 3014.6,1890 3031.69,1872.91 U1.12@3072.78,1872.91
  Bottom Layer w10: v1(1655,1505) 1790,1640 v1(1860,1640)
SCS_EEPROM: JP6a.1 R15.1 U6.1 | length 1894.2
  Top Layer w10: v1(410,1760) 470,1700 978.69,1700 v1(1340,1338.69) ; v1(410,1890) U6.1@410,2170 430.47,2149.53 R15.1@559.68,2149.53 ; JP6a.1@1419.35,1150 v1(1419.35,1259.35)
  Bottom Layer w10: v1(410,1760) v1(410,1890) ; v1(1340,1338.69) v1(1419.35,1259.35)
